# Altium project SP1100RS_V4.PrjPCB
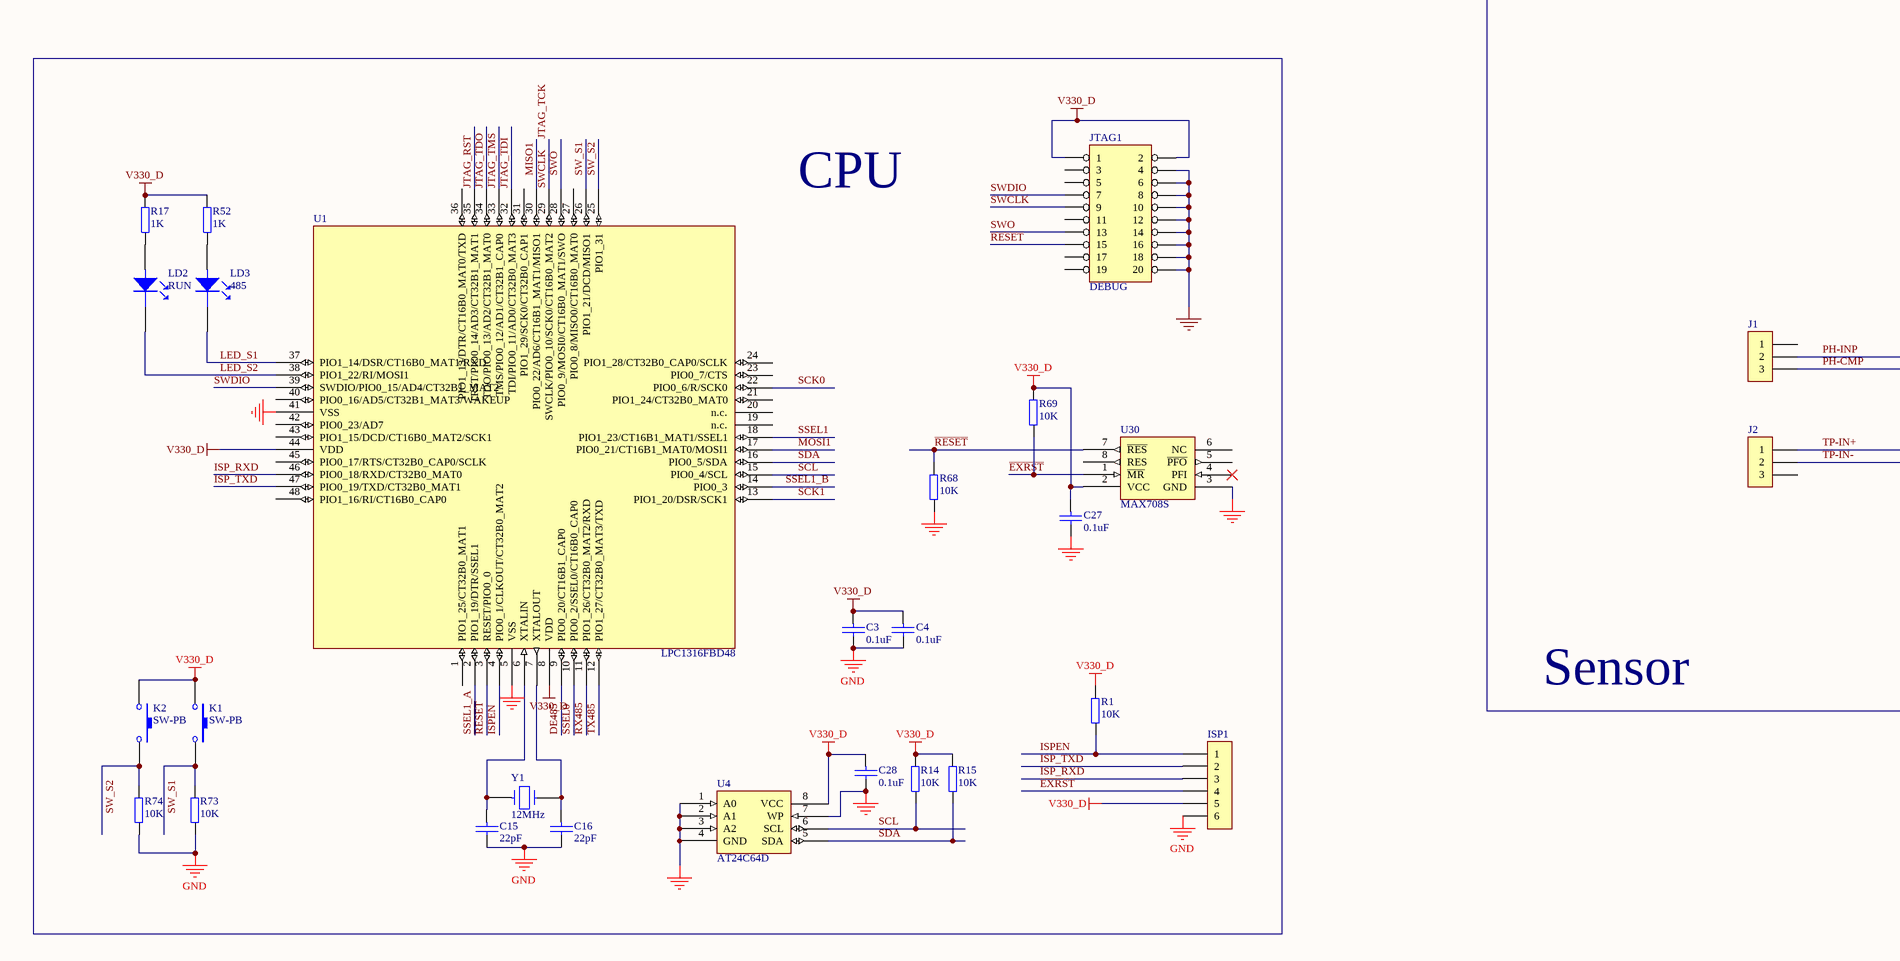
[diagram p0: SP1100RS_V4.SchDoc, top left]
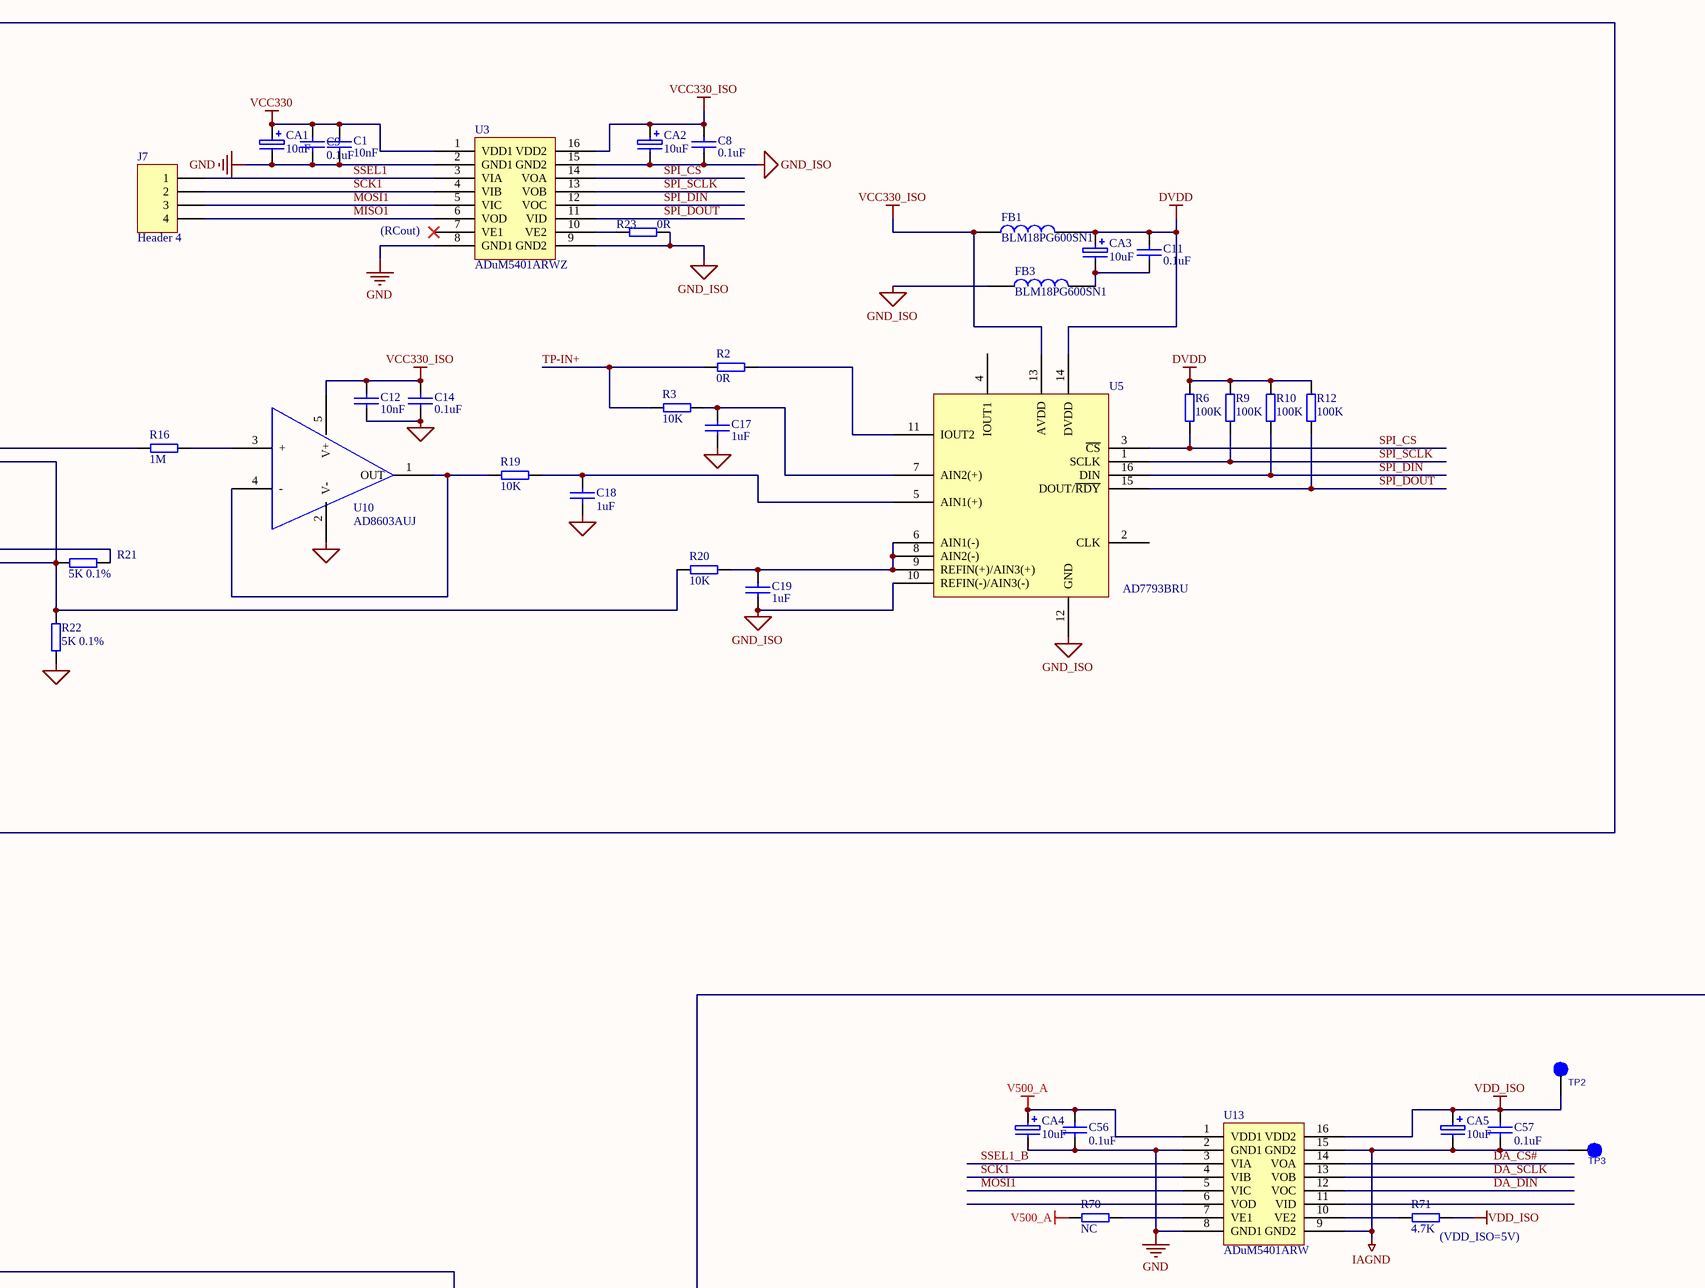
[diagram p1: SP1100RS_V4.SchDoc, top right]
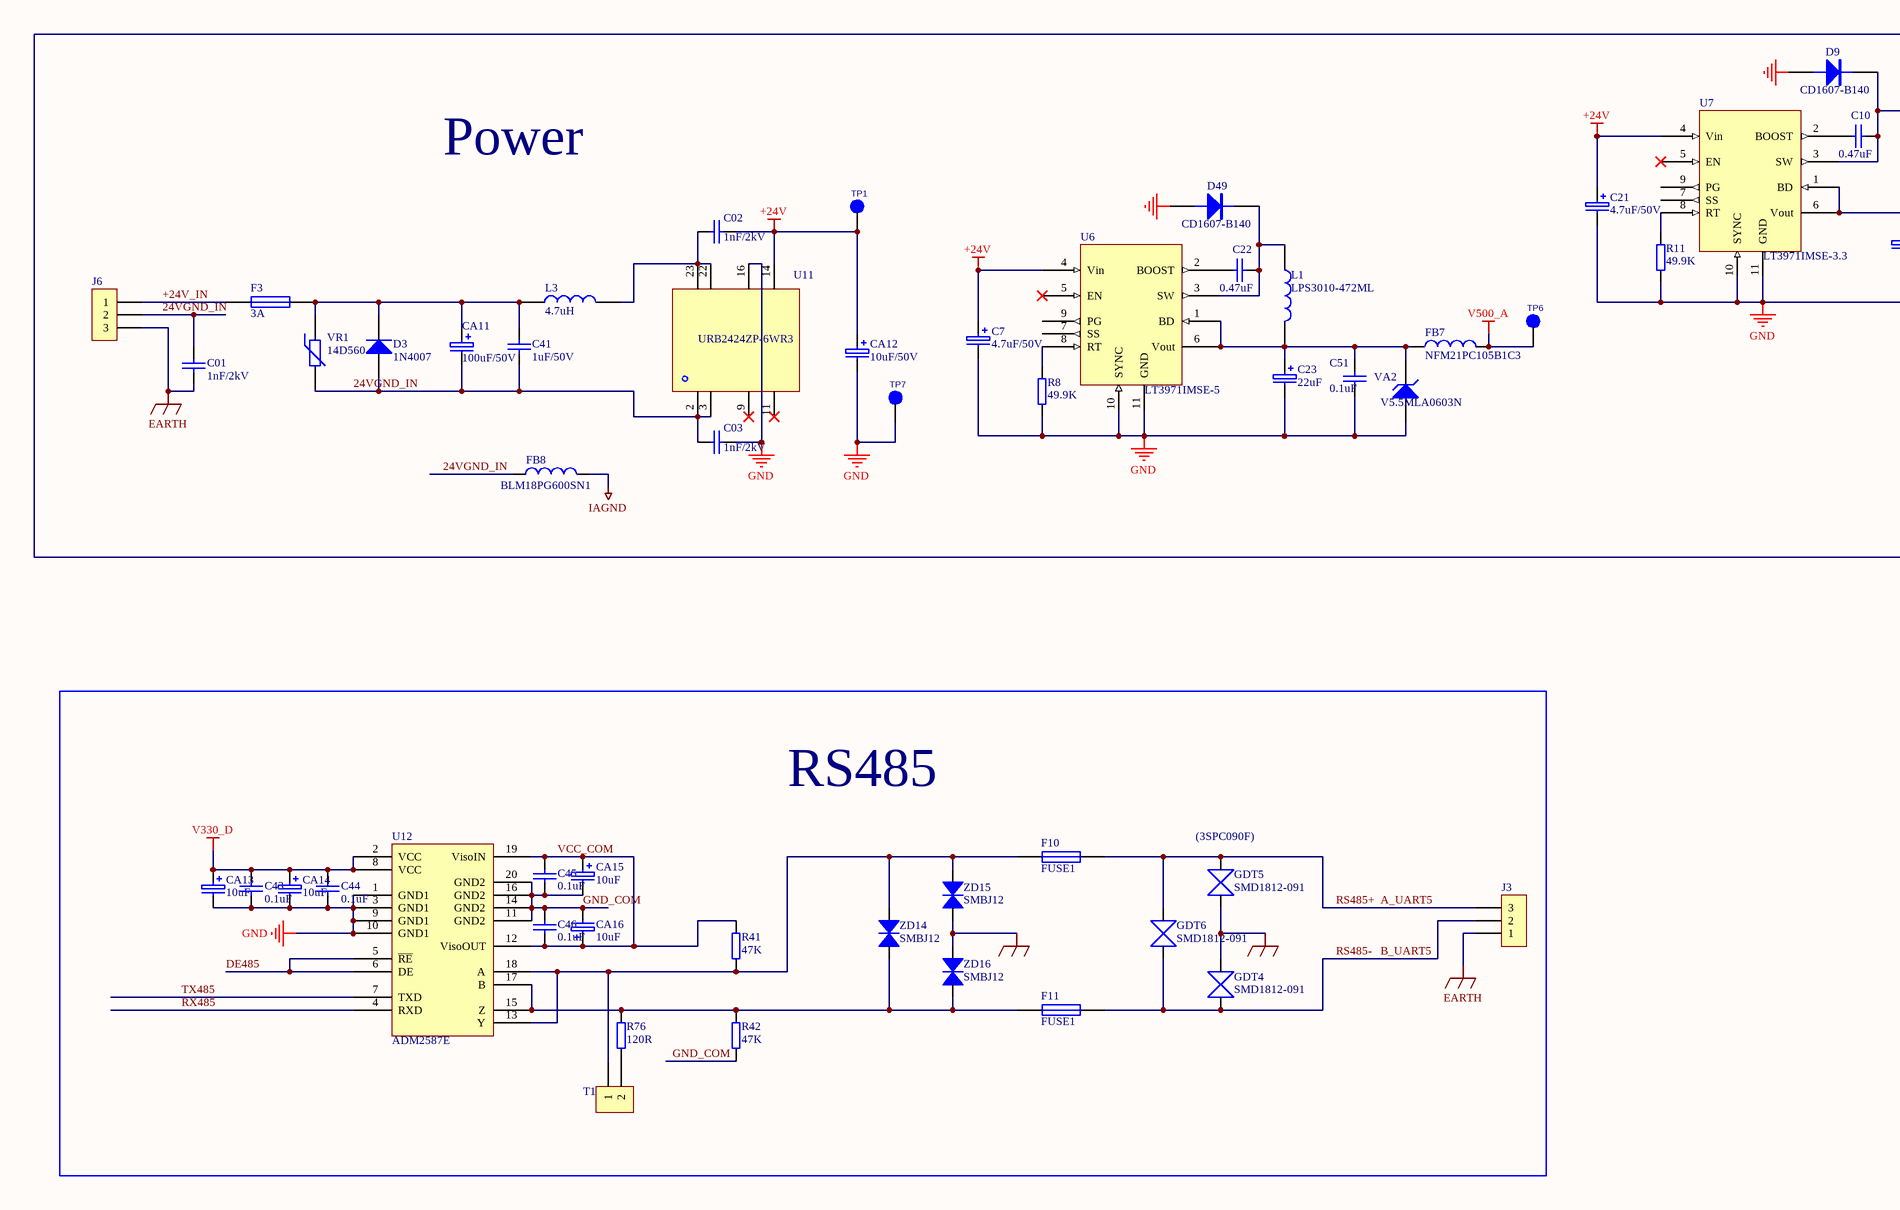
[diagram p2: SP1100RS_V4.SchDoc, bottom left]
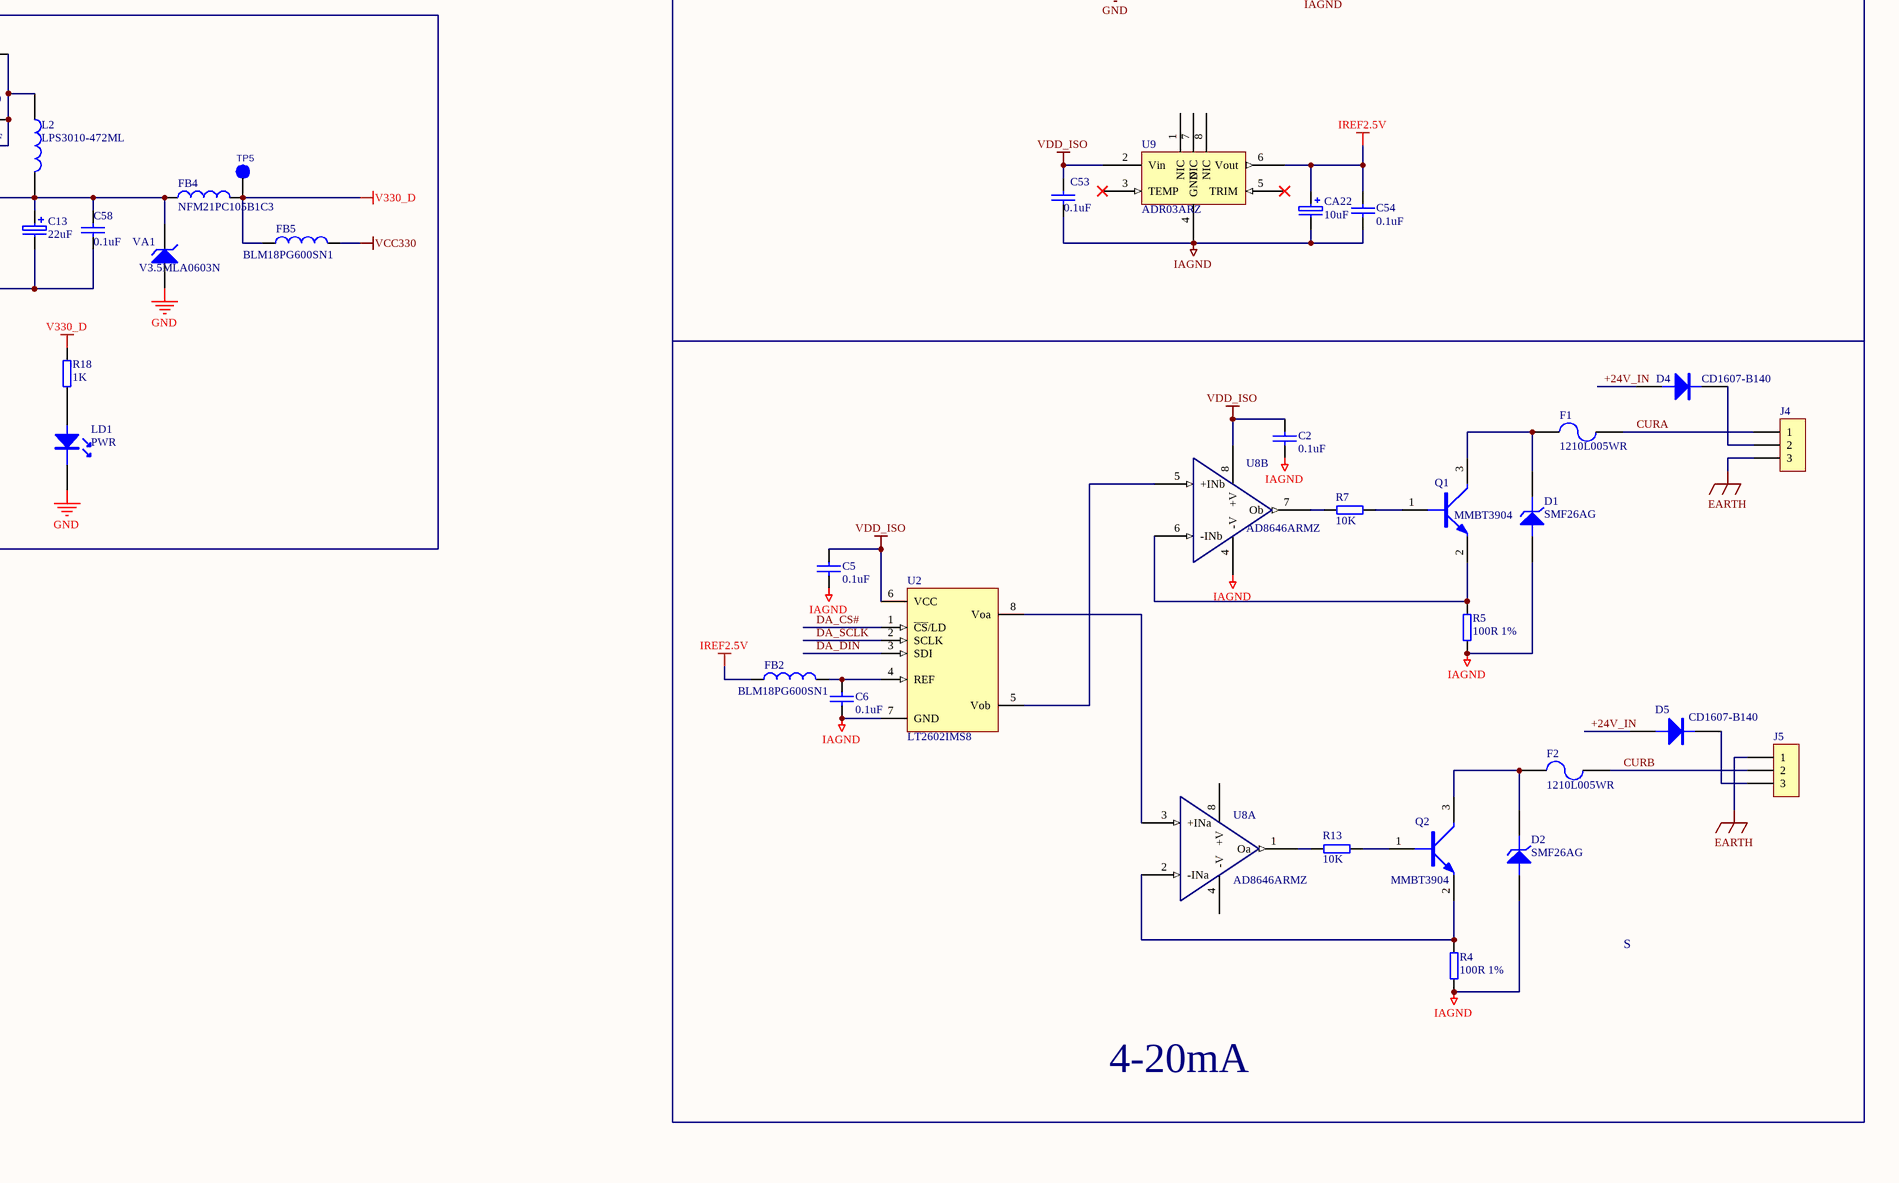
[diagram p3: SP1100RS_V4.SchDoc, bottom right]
1 sheet, 152 parts. Net scope: global (net labels, ports and power ports of the same name join across sheets).
Board file: SP1100RS_V4.1.2-ADI.PcbDoc

## Sheet SP1100RS_V4.SchDoc
size D; SheetNumber: 0; SheetTotal: 0

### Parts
C1  10nF  [0603]
C01  1nF/2kV  [1206]
C2  0.1uF  [0603]
C02  1nF/2kV  [1206]
C3  0.1uF  [0603]
C03  1nF/2kV  [1206]
C4  0.1uF  [0603]
C5  0.1uF  [0603]
C6  0.1uF  [0603]
C7  4.7uF/50V  [1206C]
C8  0.1uF  [0603]
C9  0.1uF  [0603]
C10  0.47uF  [0603]
C11  0.1uF  [0603]
C12  10nF  [0603]
C13  22uF  [1206C]
C14  0.1uF  [0603]
C15  22pF  [0603]
C16  22pF  [0603]
C17  1uF  [0603]
C18  1uF  [0603]
C19  1uF  [0603]
C21  4.7uF/50V  [1206C]
C22  0.47uF  [0603]
C23  22uF  [1206C]
C27  0.1uF  [0603]
C28  0.1uF  [0603]
C41  1uF/50V  [0805]
C43  0.1uF  [0603]
C44  0.1uF  [0603]
C45  0.1uF  [0603]
C46  0.1uF  [0603]
C51  0.1uF  [0603]
C53  0.1uF  [0603]
C54  0.1uF  [0603]
C56  0.1uF  [0603]
C57  0.1uF  [0603]
C58  0.1uF  [0603]
CA1  10uF  [1206C]
CA2  10uF  [1206C]
CA3  10uF  [1206C]
CA4  10uF  [1206]
CA5  10uF  [1206C]
CA11  100uF/50V  [D]
CA12  10uF/50V  [1206C]
CA13  10uF  [1206C]
CA14  10uF  [1206C]
CA15  10uF  [1206C]
CA16  10uF  [1206C]
CA22  10uF  [1206C]
D1  SMF26AG  [1206D]
D2  SMF26AG  [1206D]
D3  1N4007  [1N4007]
D4  CD1607-B140  [1206D]
D5  CD1607-B140  [1206D]
D9  CD1607-B140  [1206D]
D49  CD1607-B140  [1206D]
F1  1210L005WR  [1206]
F2  1210L005WR  [1206]
F3  3A  [1206]
F10  FUSE1  [1206]
F11  FUSE1  [1206]
FB1  BLM18PG600SN1  [0603]
FB2  BLM18PG600SN1  [0603]
FB3  BLM18PG600SN1  [0603]
FB4  NFM21PC105B1C3  [NFM21PC105]
FB5  BLM18PG600SN1  [0603]
FB7  NFM21PC105B1C3  [NFM21PC105]
FB8  BLM18PG600SN1  [0603]
GDT4  SMD1812-091  [1812]
GDT5  SMD1812-091  [1812]
GDT6  SMD1812-091  [1812]
ISP1  (no value)  [PH3-S]
J1  (no value)  [PH3-S]
J2  (no value)  [PH3-S]
J3  (no value)  [PH3-S]
J4  (no value)  [PH3-S]
J5  (no value)  [PH3-S]
J6  (no value)  [PH3-S]
J7  Header 4  [HDR2X2]
JTAG1  DEBUG  [IDC20]
K1  SW-PB  [SW-PB ANJIAN]
K2  SW-PB  [SW-PB ANJIAN]
L1  LPS3010-472ML  [LPS3010]
L2  LPS3010-472ML  [LPS3010]
L3  4.7uH  [LPS3010]
LD1  PWR  [LED0805]
LD2  RUN  [LED0805]
LD3  485  [LED0805]
Q1  MMBT3904  [SOT-23]
Q2  MMBT3904  [SOT-23]
R1  10K  [0603]
R2  0R  [0603]
R3  10K  [0603]
R4  100R 1%  [0603]
R5  100R 1%  [0603]
R6  100K  [0603]
R7  10K  [0603]
R8  49.9K  [0603]
R9  100K  [0603]
R10  100K  [0603]
R11  49.9K  [0603]
R12  100K  [0603]
R13  10K  [0603]
R14  10K  [0603]
R15  10K  [0603]
R16  1M  [0805]
R17  1K  [0603]
R18  1K  [0603]
R19  10K  [0603]
R20  10K  [0603]
R21  5K 0.1%  [0805]
R22  5K 0.1%  [0603]
R23  0R  [0603A]
R41  47K  [0603]
R42  47K  [0603]
R52  1K  [0603]
R68  10K  [0603]
R69  10K  [0603]
R70  NC  [0603]
R71  4.7K  [0603]
R73  10K  [0603]
R74  10K  [0603]
R76  120R  [0603]
T1  (no value)  [SIP2]
TP1  P24V  [test point]  (value not drawn)
TP2  5V_I  [test point]  (value not drawn)
TP3  GND_I  [test point]  (value not drawn)
TP5  P3.3V  [test point]  (value not drawn)
TP6  P5V  [test point]  (value not drawn)
TP7  GND  [test point]  (value not drawn)
U1  LPC1316FBD48  [LPC1316]
U2  LT2602IMS8  [LT2602]
U3  ADuM5401ARWZ  [ADUM1401]
U4  AT24C64D  [SO-8]
U5  AD7793BRU  [AD7793]
U6  LT3971IMSE-5  [LT3971]
U7  LT3971IMSE-3.3  [LT3971]
U8  AD8646ARMZ  [AD8646]  (parts A,B of 2)
U9  ADR03ARZ  [SO-8]
U10  AD8603AUJ  [AD8603]
U11  URB2424ZP-6WR3  [URB2424ZP-6WR3]
U12  ADM2587E  [SOL-20]
U13  ADuM5401ARW  [ADUM1401]
U30  MAX708S  [SO-8]
VA1  V3.5MLA0603N  [0603]
VA2  V5.5MLA0603N  [0603]
VR1  14D560  [1206]
Y1  12MHz  [CY5.4X4.6]
ZD14  SMBJ12  [ZD]
ZD15  SMBJ12  [ZD]
ZD16  SMBJ12  [ZD]

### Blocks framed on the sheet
Sensor: C1 C8 C9 C11 C12 C14 C17-C19 CA1-CA3 FB1 FB3 J1 J2 J7 R2 R3 R6 R9 R10 R12 R16 R19-R23 U3 U5 U10
CPU: C3 C4 C15 C16 C27 C28 ISP1 JTAG1 K1 K2 LD2 LD3 R1 R14 R15 R17 R52 R68 R69 R73 R74 U1 U4 U30 Y1
Power: C01 C02 C03 C7 C10 C13 C21-C23 C41 C51 C58 CA11 CA12 D3 D9 D49 F3 FB4 FB5 FB7 FB8 J6 L1-L3 LD1 R8 R11 R18 TP1 TP5-TP7 U6 U7 U11 VA1 VA2 VR1
RS485: C43-C46 CA13-CA16 F10 F11 GDT4-GDT6 J3 R41 R42 R76 T1 U12 ZD14-ZD16

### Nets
+24V: C02.1 C7.1 C21.1 CA12.1 TP1.1 U6.4(Vin) U7.4(Vin) U11.14
DVDD: C11.1 CA3.1 FB1.2 R6.1 R9.1 R10.1 R12.1 U5.14(DVDD)
EARTH: C01.2 GDT4.2 GDT5.1 J3.1 J4.3 J5.1 J6.3 ZD15.2 ZD16.1
GND: C1.2 C03.1 C3.2 C4.2 C7.2 C9.1 C13.2 C15.2 C16.2 C21.2 C23.2 C27.2 C28.2 C43.2 C44.2 C51.2 C56.2 C58.2 CA1.2 CA4.2 CA12.2 CA13.2 CA14.2 D9.1(A) D49.1(A) ISP1.6 JTAG1.4 JTAG1.6 JTAG1.8 JTAG1.10 JTAG1.12 JTAG1.14 JTAG1.16 JTAG1.18 JTAG1.20 LD1.K R8.1 R11.1 R68.1 R73.1 R74.1 TP7.1 U1.5(VSS) U1.41(VSS) U3.2(GND1) U3.8(GND1) U4.1(A0) U4.2(A1) U4.3(A2) U4.4(GND) U4.7(WP) U6.10(SYNC) U6.11(GND) U7.10(SYNC) U7.11(GND) U11.16 U12.1(GND1) U12.3(GND1) U12.9(GND1) U12.10(GND1) U13.2(GND1) U13.8(GND1) U30.3(GND) VA1.1(A) VA2.1(A)
GND_ISO: C8.2 C12.2 C14.2 C17.2 C18.2 C19.2 CA2.2 FB3.1 R22.2 R23.2 U3.9(GND2) U3.15(GND2) U5.10(REFIN(-)/AIN3(-)) U5.12(GND) U10.2(V-)
IAGND: C2.2 C5.2 C6.2 C53.2 C54.2 C57.2 CA5.2 CA22.2 D1.1(A) D2.1(A) FB8.2 R4.2 R5.2 TP3.1 U2.7(GND) U8.4(-V) U9.4(GND) U13.9(GND2) U13.15(GND2)
IREF2.5V: C54.1 CA22.1 FB2.1 U9.6(Vout)
NIC: U9.1(NIC) U9.7(NIC) U9.8(NIC)
V330_D: C3.1 C4.1 C27.1 C28.1 C43.1 C44.1 CA13.1 CA14.1 FB4.2 FB5.1 ISP1.5 JTAG1.1 JTAG1.2 K1.1 K2.1 R1.2 R14.2 R15.2 R17.2 R18.2 R52.2 R69.2 TP5.1 U1.8(VDD) U1.44(VDD) U4.8(VCC) U12.2(VCC) U12.8(VCC) U30.2(VCC)
V500_A: C56.1 CA4.1 FB7.2 R70.2 TP6.1 U13.1(VDD1)
VCC330: C1.1 C9.2 CA1.1 FB5.2 U3.1(VDD1)
VCC330_ISO: C8.1 C12.1 C14.1 CA2.1 FB1.1 U3.16(VDD2) U5.13(AVDD) U10.5(V+)
VDD_ISO: C2.1 C5.1 C53.1 C57.1 CA5.1 R71.1 TP2.1 U2.6(VCC) U8.8(+V) U9.2(Vin) U13.16(VDD2)
24VGND_IN: C01.1 C03.2 C41.2 CA11.2 D3.1(A) FB8.1 J6.2 U11.2 U11.3 VR1.2
+24V_IN: D4.1(A) D5.1(A) F3.1 J6.1
A_UART5: F10.2 GDT5.2 GDT6.2 J3.3  [also labelled RS485+]
B_UART5: F11.2 GDT4.1 GDT6.1 J3.2  [also labelled RS485-]
CURA: F1.2 J4.1
CURB: F2.2 J5.2
DA_CS#: U2.1(~{CS}/LD) U13.14(VOA)
DA_DIN: U2.3(SDI) U13.12(VOC)
DA_SCLK: U2.2(SCLK) U13.13(VOB)
DE485: U1.9(PIO0_20/CT16B1_CAP0) U12.5(~{RE}) U12.6(DE)
~{EXRST}: ISP1.4 R69.1 U30.1(~{MR})
GND_COM: C45.2 C46.1 CA15.2 CA16.2 R42.2 U12.11(GND2) U12.14(GND2) U12.16(GND2) U12.20(GND2)
ISP_RXD: ISP1.3 U1.46(PIO0_18/RXD/CT32B0_MAT0)
ISP_TXD: ISP1.2 U1.47(PIO0_19/TXD/CT32B0_MAT1)
ISPEN: ISP1.1 R1.1 U1.4(PIO0_1/CLKOUT/CT32B0_MAT2)
JTAG_RST: U1.35(TRST/PIO0_14/AD3/CT32B1_MAT1)
JTAG_TCK: JTAG1.9 U1.29(SWCLK/PIO0_10/SCK0/CT16B0_MAT2)  [also labelled SWCLK]
JTAG_TDI: U1.32(TDI/PIO0_11/AD0/CT32B0_MAT3)
JTAG_TDO: U1.34(TDO/PIO0_13/AD2/CT32B1_MAT0)
JTAG_TMS: U1.33(TMS/PIO0_12/AD1/CT32B1_CAP0)
LED_S1: LD3.K U1.37(PIO1_14/DSR/CT16B0_MAT1/RXD)
LED_S2: LD2.K U1.38(PIO1_22/RI/MOSI1)
MISO1: J7.4 U1.30(PIO0_22/AD6/CT16B1_MAT1/MISO1) U3.6(VOD)
MOSI1: J7.3 U1.17(PIO0_21/CT16B1_MAT0/MOSI1) U3.5(VIC) U13.5(VIC)
PH-CMP: J1.3 J2.2 R20.1 R21.1 R22.1  [also labelled TP-IN-]
PH-INP: J1.2 R16.1
~{RESET}: JTAG1.15 R68.2 U1.3(RESET/PIO0_0) U30.7(~{RES})
RX485: U1.11(PIO1_26/CT32B0_MAT2/RXD) U12.4(RXD)
SCK0: U1.22(PIO0_6/R/SCK0)
SCK1: J7.2 U1.13(PIO1_20/DSR/SCK1) U3.4(VIB) U13.4(VIB)
SCL: R14.1 U1.15(PIO0_4/SCL) U4.6(SCL)
SDA: R15.1 U1.16(PIO0_5/SDA) U4.5(SDA)
SPI_CS: R6.2 U3.14(VOA) U5.3(~{CS})
SPI_DIN: R10.2 U3.12(VOC) U5.16(DIN)
SPI_DOUT: R12.2 U3.11(VID) U5.15(DOUT/~{RDY})
SPI_SCLK: R9.2 U3.13(VOB) U5.1(SCLK)
SSEL0: U1.10(PIO0_2/SSEL0/CT16B0_CAP0)
SSEL1: J7.1 U1.18(PIO1_23/CT16B1_MAT1/SSEL1) U3.3(VIA)
SSEL1_A: U1.2(PIO1_19/DTR/SSEL1)
SSEL1_B: U1.14(PIO0_3) U13.3(VIA)
SW_S1: K1.2 R73.2 U1.26(PIO1_21/DCD/MISO1)
SW_S2: K2.2 R74.2 U1.25(PIO1_31)
SWDIO: JTAG1.7 U1.39(SWDIO/PIO0_15/AD4/CT32B1_MAT2)
SWO: JTAG1.13 U1.28(PIO0_9/MOSI0/CT16B0_MAT1/SWO)
TP-IN+: J2.1 R2.1 R3.1 R21.2
TX485: U1.12(PIO1_27/CT32B0_MAT3/TXD) U12.7(TXD)
VCC_COM: C45.1 C46.2 CA15.1 CA16.1 R41.1 U12.12(VisoOUT) U12.19(VisoIN)
NetC02_2: C02.2 L3.2 U11.22 U11.23
NetC6_1: C6.1 FB2.2 U2.4(REF)
NetC10_1: C10.1 U7.2(BOOST)
NetC10_2: C10.2 D9.2(K) L2.1 U7.3(SW)
NetC11_2: C11.2 CA3.2 FB3.2
NetC13_1: C13.1 C58.1 FB4.1 L2.2 U7.1(BD) U7.6(Vout) VA1.2(K)
NetC15_1: C15.1 U1.6(XTALIN) Y1.1
NetC16_1: C16.1 U1.7(XTALOUT) Y1.2
NetC17_1: C17.1 R3.2 U5.7(AIN2(+))
NetC18_1: C18.1 R19.2 U5.5(AIN1(+))
NetC19_1: C19.1 R20.2 U5.6(AIN1(-)) U5.8(AIN2(-)) U5.9(REFIN(+)/AIN3(+))
NetC22_1: C22.1 U6.2(BOOST)
NetC22_2: C22.2 D49.2(K) L1.1 U6.3(SW)
NetC23_1: C23.1 C51.1 FB7.1 L1.2 U6.1(BD) U6.6(Vout) VA2.2(K)
NetC41_1: C41.1 CA11.1 D3.2(K) F3.2 L3.1 VR1.1
NetD1_2: D1.2(K) F1.1 Q1.3(C)
NetD2_2: D2.2(K) F2.1 Q2.3(C)
NetD4_2: D4.2(K) J4.2
NetD5_2: D5.2(K) J5.3
NetF10_1: F10.1 R41.2 T1.1 U12.13(Y) U12.18(A) ZD14.1 ZD15.1
NetF11_1: F11.1 R42.1 R76.1 U12.15(Z) U12.17(B) ZD14.2 ZD16.2
NetLD1_A: LD1.A R18.1
NetLD2_A: LD2.A R17.1
NetLD3_A: LD3.A R52.1
NetQ1_1: Q1.1(B) R7.1
NetQ1_2: Q1.2(E) R5.1 U8.6(-INb)
NetQ2_1: Q2.1(B) R13.1
NetQ2_2: Q2.2(E) R4.1 U8.2(-INa)
NetR2_2: R2.2 U5.11(IOUT2)
NetR7_2: R7.2 U8.7(Ob)
NetR8_2: R8.2 U6.8(RT)
NetR11_2: R11.2 U7.8(RT)
NetR13_2: R13.2 U8.1(Oa)
NetR16_2: R16.2 U10.3(+)
NetR19_1: R19.1 U10.1(OUT) U10.4(-)
NetR23_1: R23.1 U3.10(VE2)
NetR70_1: R70.1 U13.7(VE1)
NetR71_2: R71.2 U13.10(VE2)
NetR76_2: R76.2 T1.2
NetU2_5: U2.5(Vob) U8.5(+INb)
NetU2_8: U2.8(Voa) U8.3(+INa)

Not connected (* = marked no-connect by the designer): J1 1; J2 3; JTAG1 3 5 11 17 19; U1 1(PIO1_25/CT32B0_MAT1) 19(n.c.) 20(n.c.) 21(PIO1_24/CT32B0_MAT0) 23(PIO0_7/CTS) 24(PIO1_28/CT32B0_CAP0/SCLK) 27(PIO0_8/MISO0/CT16B0_MAT0) 31(PIO1_29/SCK0/CT32B0_CAP1) 36(PIO1_13/DTR/CT16B0_MAT0/TXD) 40(PIO0_16/AD5/CT32B1_MAT3/WAKEUP) 42(PIO0_23/AD7) 43(PIO1_15/DCD/CT16B0_MAT2/SCK1) 45(PIO0_17/RTS/CT32B0_CAP0/SCLK) 48(PIO1_16/RI/CT16B0_CAP0); U3 7(VE1)*; U5 2(CLK) 4(IOUT1); U6 5(EN)* 7(SS) 9(PG); U7 5(EN)* 7(SS) 9(PG); U9 3(TEMP)* 5(TRIM)*; U11 9* 11*; U13 6(VOD) 11(VID); U30 4(PFI)* 5(~{PFO}) 6(NC) 8(RES)

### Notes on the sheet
- (near U3) (RCout)
- (near R71) (VDD_ISO=5V)
- (near GDT5) (3SPC090F)
- S
- 4-20mA

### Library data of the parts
C1 C8 C9 C11 C12 C14 C17-C19 = C: 电容
C01 C2 C02 C3 C03-C6 C10 C15 C16 C22 C27 C28 C41 C51 C53 C54 C56-C58 = CAP: Capacitor
C7 C13 C21 C23 CA13-CA16 CA22 = C: 极性电容
C43-C46 = CA: 电容
CA1-CA5 CA11 CA12 = CAPE: 极性电容
D1 D2 = ZENER3: Zener Diode
D3 = Diode 1N4007: 1 Amp General Purpose Rectifier
D4 D5 D9 D49 = DIODE
F1 F2 = FUSE2: Fuse
F3 F10 F11 = FUSE1: Fuse
FB1 FB3 L1-L3 = INDUCTOR
FB2 FB4 FB5 FB7 FB8 = Inductor: Code_IEC: 1005; Value: 10mH
GDT4-GDT6 = BT90
ISP1 = CON6: Connector
J1-J6 = CON3: Connector
J7 = Header 4: Header, 4-Pin
JTAG1 = HEADER 10X2
K1 K2 = SW-PB: Switch
LD1-LD3 = LED
R1 R4 R5 R7 R8 R11 R13-R15 R17 R18 R52 R68-R71 R73 R74 = RES: 电阻
R2 R3 R6 R9 R10 R12 R16 R19-R23 = R: 电阻
R41 R42 R76 = RE: 电阻
T1 = CON2: Connector
TP1-TP3 TP5-TP7 = PAD
U2 = LT2602
U3 U13 = ADUM1401: 1Mbps Data Rate, 100ns Propagation delay
U4 = 24C01/02/04/08/16
U5 = AD7793
U6 U7 = LT3971
U8 = AD8646
U9 = ADR02
U10 = AD8603
U30 = SP708
VA1 VA2 = D Zener: Zener Diode
VR1 = Res Varistor: Varistor (Voltage-Sensitive Resistor)
Y1 = CRYSTAL
ZD14-ZD16 = SMBJ: 瞬变抑制二极管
